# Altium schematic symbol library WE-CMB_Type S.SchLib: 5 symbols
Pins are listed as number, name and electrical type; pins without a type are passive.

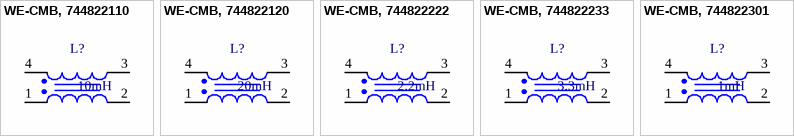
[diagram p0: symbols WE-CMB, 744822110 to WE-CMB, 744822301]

## WE-CMB, 744822110
designator L?, comment 10mH
WE-CMB Common Mode Power Line Choke, Type S, 10mH; PartNumber: 744822110
footprint WE-CMB_Type S
pins: 1, 2, 3, 4

## WE-CMB, 744822120
designator L?, comment 20mH
WE-CMB Common Mode Power Line Choke, Type S, 20mH; PartNumber: 744822120
footprint WE-CMB_Type S
pins: 1, 2, 3, 4

## WE-CMB, 744822222
designator L?, comment 2.2mH
WE-CMB Common Mode Power Line Choke, Type S, 2.2mH; PartNumber: 744822222
footprint WE-CMB_Type S
pins: 1, 2, 3, 4

## WE-CMB, 744822233
designator L?, comment 3.3mH
WE-CMB Common Mode Power Line Choke, Type S, 3.3mH; PartNumber: 744822233
footprint WE-CMB_Type S
pins: 1, 2, 3, 4

## WE-CMB, 744822301
designator L?, comment 1mH
WE-CMB Common Mode Power Line Choke, Type S, 1mH; PartNumber: 744822301
footprint WE-CMB_Type S
pins: 1, 2, 3, 4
